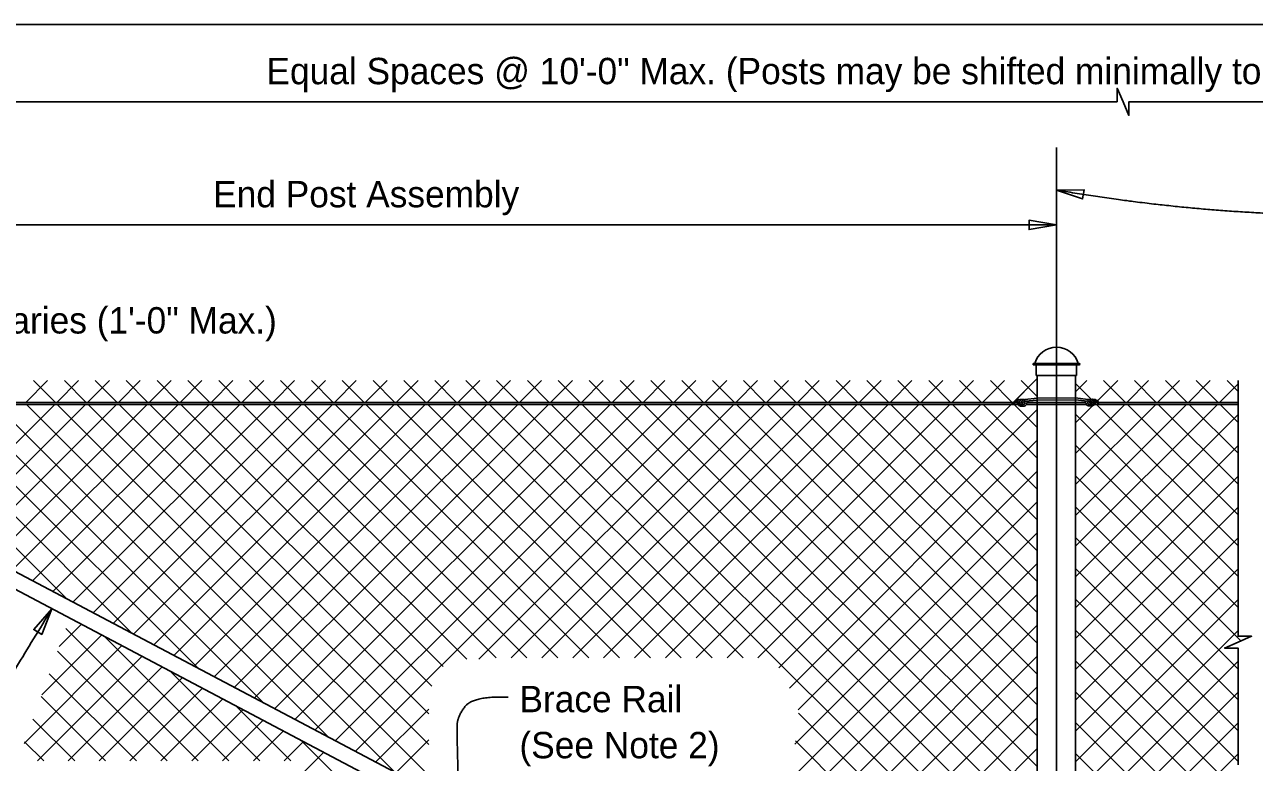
# Model space of a CAD drawing. Extents: x 0 to 41.1, y 0 to 25.9.
# Drawn here: x 6.74 to 16.13, y 20.31 to 25.95 of the extents above; entities that cross this region are included whole.
import ezdxf

# ---------------------------------------------------------------- set-up
doc = ezdxf.new("R2010")
doc.units = 0
for name, color, linetype in [('ActivePts-ConstElements', 7, 'Continuous'), ('CL_Major', 7, 'Continuous'), ('Dimension', 7, 'Continuous'), ('Miscellaneous', 7, 'Continuous'), ('Miscellaneous1', 7, 'Continuous'), ('SteelMisc', 7, 'Continuous'), ('SteelMisc_h', 7, 'Continuous'), ('TextStructures', 7, 'Continuous')]:
    doc.layers.add(name, color=color, linetype=linetype)

msp = doc.modelspace()

# ---------------------------------------------------------------- linework, layer by layer
at = {"layer": 'ActivePts-ConstElements'}
msp.add_lwpolyline([(0, 0), (41.0506, 0), (41.0506, 25.9461), (0, 25.9461)], close=True, dxfattribs=at)
at = {"layer": 'CL_Major'}
msp.add_line((14.615, 25.0052), (14.615, 14.7584), dxfattribs=at)
at = {"layer": 'Dimension'}
for p, q in [((0.2352, 25.3556), (13.615, 25.3556)), ((4.615, 24.4146), (14.615, 24.4146))]:
    msp.add_line(p, q, dxfattribs=at)
for points in [[(13.615, 25.3556), (15.0787, 25.3556), (15.0787, 25.4589), (15.1237, 25.3556), (15.1687, 25.2523), (15.1687, 25.3556), (28.4596, 25.3556)], [(16.002, 23.2265), (16.002, 21.2702), (16.1053, 21.2702), (16.002, 21.2252), (15.8987, 21.1802), (16.002, 21.1802), (16.002, 20.2867)]]:
    msp.add_lwpolyline(points, dxfattribs=at)
for points in [[(14.615, 24.6814), (14.815, 24.6135), (14.8262, 24.6832)], [(14.615, 24.4146), (14.4068, 24.4499), (14.4068, 24.3793)], [(6.945, 21.4806), (6.8059, 21.3216), (6.8661, 21.2847)]]:
    msp.add_lwpolyline(points, close=True, dxfattribs=at)
for points in [[(18.5966, 24.4827), (17.7933, 24.4827), (16.4039, 24.4827), (15.2225, 24.5773), (14.615, 24.6814)], [(6.6174, 20.081), (6.4865, 20.0669), (6.3036, 20.1341), (6.3121, 20.4608), (6.945, 21.4806)], [(10.4281, 20.8052), (10.1586, 20.8133), (10.0405, 20.6549), (10.0376, 20.5337), (10.0422, 20.3659), (10.0503, 19.9529)]]:
    msp.add_open_spline(points, degree=2, dxfattribs=at)
at = {"layer": 'Miscellaneous'}
for p, q in [((6.745, 23.0578), (6.9116, 23.2245)), ((6.8042, 23.2245), (6.9709, 23.0578)), ((6.9807, 23.0578), (7.1473, 23.2245)), ((7.0399, 23.2245), (7.2066, 23.0578)), ((7.2164, 23.0578), (7.383, 23.2245)), ((7.2756, 23.2245), (7.4423, 23.0578)), ((7.4521, 23.0578), (7.6187, 23.2245)), ((7.5113, 23.2245), (7.678, 23.0578)), ((7.6878, 23.0578), (7.8544, 23.2245)), ((7.747, 23.2245), (7.9137, 23.0578)), ((7.9235, 23.0578), (8.0901, 23.2245)), ((7.9827, 23.2245), (8.1494, 23.0578)), ((8.1592, 23.0578), (8.3258, 23.2245)), ((8.2184, 23.2245), (8.3851, 23.0578)), ((8.3949, 23.0578), (8.5615, 23.2245)), ((8.4541, 23.2245), (8.6208, 23.0578)), ((8.6306, 23.0578), (8.7972, 23.2245)), ((8.6898, 23.2245), (8.8565, 23.0578)), ((8.8663, 23.0578), (9.0329, 23.2245)), ((8.9255, 23.2245), (9.0922, 23.0578)), ((9.102, 23.0578), (9.2687, 23.2245)), ((9.1612, 23.2245), (9.3279, 23.0578)), ((9.3377, 23.0578), (9.5044, 23.2245)), ((9.3969, 23.2245), (9.5636, 23.0578)), ((9.5734, 23.0578), (9.7401, 23.2245)), ((9.6326, 23.2245), (9.7993, 23.0578)), ((9.8091, 23.0578), (9.9758, 23.2245)), ((9.8683, 23.2245), (10.035, 23.0578)), ((10.0448, 23.0578), (10.2115, 23.2245)), ((10.104, 23.2245), (10.2707, 23.0578)), ((10.2805, 23.0578), (10.4472, 23.2245)), ((10.3397, 23.2245), (10.5064, 23.0578)), ((10.5162, 23.0578), (10.6829, 23.2245)), ((10.5754, 23.2245), (10.7421, 23.0578)), ((10.7519, 23.0578), (10.9186, 23.2245)), ((10.8111, 23.2245), (10.9778, 23.0578)), ((10.9876, 23.0578), (11.1543, 23.2245)), ((11.0468, 23.2245), (11.2135, 23.0578)), ((11.2233, 23.0578), (11.39, 23.2245)), ((11.2825, 23.2245), (11.4492, 23.0578)), ((11.459, 23.0578), (11.6257, 23.2245)), ((11.5182, 23.2245), (11.6849, 23.0578)), ((11.6947, 23.0578), (11.8614, 23.2245)), ((11.7539, 23.2245), (11.9206, 23.0578)), ((11.9304, 23.0578), (12.0971, 23.2245)), ((11.9896, 23.2245), (12.1563, 23.0578)), ((12.1661, 23.0578), (12.3328, 23.2245)), ((12.2253, 23.2245), (12.392, 23.0578)), ((12.336, 21.1064), (14.4692, 23.2396)), ((12.4018, 23.0578), (12.5685, 23.2245)), ((12.461, 23.2245), (12.6277, 23.0578)), ((12.6375, 23.0578), (12.8042, 23.2245)), ((12.6967, 23.2245), (12.8634, 23.0578)), ((12.8732, 23.0578), (13.0399, 23.2245)), ((12.9324, 23.2245), (13.0991, 23.0578)), ((13.1089, 23.0578), (13.2756, 23.2245)), ((13.1681, 23.2245), (13.3348, 23.0578)), ((13.3446, 23.0578), (13.5113, 23.2245)), ((13.4038, 23.2245), (13.5705, 23.0578)), ((13.5803, 23.0578), (13.747, 23.2245)), ((13.6396, 23.2245), (13.8062, 23.0578)), ((13.816, 23.0578), (13.9827, 23.2245)), ((13.8753, 23.2245), (14.0419, 23.0578)), ((14.0517, 23.0578), (14.2184, 23.2245)), ((14.111, 23.2245), (14.2776, 23.0578)), ((14.2874, 23.0578), (14.4541, 23.2245)), ((14.3467, 23.2245), (14.4692, 23.1019)), ((14.7609, 23.1379), (14.8475, 23.2245)), ((14.7609, 23.2036), (14.8832, 23.0814)), ((14.928, 23.0694), (15.0832, 23.2245)), ((14.9757, 23.2245), (15.1424, 23.0578)), ((15.1522, 23.0578), (15.3189, 23.2245)), ((15.2114, 23.2245), (15.3781, 23.0578)), ((15.3879, 23.0578), (15.5546, 23.2245)), ((15.4471, 23.2245), (15.6138, 23.0578)), ((15.6236, 23.0578), (15.7903, 23.2245)), ((15.6828, 23.2245), (15.8495, 23.0578)), ((15.8593, 23.0578), (16.002, 23.2005)), ((15.9185, 23.2245), (16.002, 23.1411)), ((5.8071, 23.0431), (7.5577, 21.2925)), ((6.0252, 22.1023), (6.9659, 23.0431)), ((6.0428, 23.0431), (8.0575, 21.0283)), ((6.1794, 22.0209), (7.2016, 23.0431)), ((6.2785, 23.0431), (8.5574, 20.7642)), ((6.3336, 21.9394), (7.4373, 23.0431)), ((6.4878, 21.8579), (7.673, 23.0431)), ((6.5142, 23.0431), (9.0572, 20.5)), ((6.642, 21.7764), (7.9087, 23.0431)), ((6.7499, 23.0431), (9.5571, 20.2359)), ((6.7962, 21.6949), (8.1444, 23.0431)), ((6.9504, 21.6134), (8.3801, 23.0431)), ((6.9856, 23.0431), (9.8224, 20.2063)), ((7.1046, 21.5319), (8.6158, 23.0431)), ((7.2213, 23.0431), (9.8224, 20.442)), ((7.2589, 21.4504), (8.8515, 23.0431)), ((7.4131, 21.3689), (9.0872, 23.0431)), ((7.457, 23.0431), (9.8224, 20.6777)), ((7.5673, 21.2874), (9.3229, 23.0431)), ((7.6927, 23.0431), (9.8467, 20.8891)), ((7.7215, 21.2059), (9.5586, 23.0431)), ((7.8757, 21.1244), (9.7943, 23.0431)), ((7.9284, 23.0431), (9.9312, 21.0403)), ((8.0299, 21.0429), (10.03, 23.0431)), ((8.1641, 23.0431), (10.1124, 21.0948)), ((8.1841, 20.9614), (10.2657, 23.0431)), ((8.3383, 20.88), (10.5014, 23.0431)), ((8.3998, 23.0431), (10.3365, 21.1064)), ((8.4925, 20.7985), (10.7372, 23.0431)), ((8.6355, 23.0431), (10.5722, 21.1064)), ((8.6467, 20.717), (10.9729, 23.0431)), ((8.8009, 20.6355), (11.2086, 23.0431)), ((8.8712, 23.0431), (10.8079, 21.1064)), ((8.9552, 20.554), (11.4443, 23.0431)), ((9.1069, 23.0431), (11.0436, 21.1064)), ((9.1094, 20.4725), (11.68, 23.0431)), ((9.2636, 20.391), (11.9157, 23.0431)), ((9.3426, 23.0431), (11.2793, 21.1064)), ((9.5783, 23.0431), (11.515, 21.1064)), ((9.814, 23.0431), (11.7507, 21.1064)), ((10.0497, 23.0431), (11.9864, 21.1064)), ((10.2043, 21.096), (12.1514, 23.0431)), ((10.2854, 23.0431), (12.2221, 21.1064)), ((10.4504, 21.1064), (12.3871, 23.0431)), ((10.5211, 23.0431), (14.4692, 19.095)), ((10.6861, 21.1064), (12.6228, 23.0431)), ((10.7568, 23.0431), (14.4692, 19.3307)), ((10.9218, 21.1064), (12.8585, 23.0431)), ((10.9925, 23.0431), (14.4692, 19.5664)), ((11.1575, 21.1064), (13.0942, 23.0431)), ((11.2282, 23.0431), (14.4692, 19.8021)), ((11.3932, 21.1064), (13.3299, 23.0431)), ((11.4639, 23.0431), (14.4692, 20.0378)), ((11.6289, 21.1064), (13.5656, 23.0431)), ((11.6996, 23.0431), (14.4692, 20.2735)), ((11.8646, 21.1064), (13.8013, 23.0431)), ((11.9353, 23.0431), (14.4692, 20.5092)), ((12.1003, 21.1064), (14.037, 23.0431)), ((12.1003, 21.1064), (14.037, 23.0431)), ((12.1711, 23.0431), (14.4692, 20.7449)), ((12.4068, 23.0431), (14.4692, 20.9806)), ((12.6425, 23.0431), (14.4692, 21.2163)), ((12.8782, 23.0431), (14.4692, 21.452)), ((13.1139, 23.0431), (14.4692, 21.6877)), ((13.3496, 23.0431), (14.4692, 21.9234)), ((13.5853, 23.0431), (14.4692, 22.1591)), ((13.821, 23.0431), (14.4692, 22.3948)), ((14.0567, 23.0431), (14.4692, 22.6305)), ((14.2924, 23.0431), (14.4692, 22.8662)), ((14.7609, 21.9594), (15.8446, 23.0431)), ((14.7609, 22.4308), (15.3732, 23.0431)), ((14.7609, 22.6665), (15.1375, 23.0431)), ((14.7609, 22.9022), (14.8904, 23.0317)), ((14.7653, 22.1995), (15.6089, 23.0431)), ((14.9165, 23.0578), (14.921, 23.0623)), ((14.9214, 23.0431), (16.002, 21.9626)), ((15.1572, 23.0431), (16.002, 22.1983)), ((15.3929, 23.0431), (16.002, 22.434)), ((15.6286, 23.0431), (16.002, 22.6697)), ((15.8643, 23.0431), (16.002, 22.9054)), ((12.4951, 21.0298), (14.4692, 23.0039)), ((14.7609, 22.9679), (16.002, 21.7268)), ((14.7609, 21.7237), (16.002, 22.9648)), ((5.7518, 22.8627), (7.0578, 21.5566)), ((12.5756, 20.8746), (14.4692, 22.7682)), ((14.7609, 22.7322), (16.002, 21.4911)), ((14.7609, 21.488), (16.002, 22.7291)), ((12.6439, 20.7072), (14.4692, 22.5325)), ((14.7609, 22.4965), (16.023, 21.2344)), ((14.7609, 21.2523), (16.002, 22.4934)), ((12.6167, 20.4443), (14.4692, 22.2968)), ((14.7609, 22.2608), (16.002, 21.0197)), ((14.7609, 21.0166), (16.002, 22.2577)), ((11.5767, 19.1686), (14.4692, 22.0611)), ((14.7609, 22.0251), (16.002, 20.784)), ((14.7609, 20.7809), (16.002, 22.022)), ((11.7309, 19.0871), (14.4692, 21.8254)), ((14.7609, 21.7894), (16.002, 20.5483)), ((14.7609, 20.5452), (16.002, 21.7863)), ((11.8851, 19.0056), (14.4692, 21.5897)), ((14.7609, 21.5537), (16.002, 20.3126)), ((14.7609, 20.3095), (16.002, 21.5506)), ((7.0006, 21.1922), (7.1701, 21.3617)), ((7.0502, 21.3286), (8.0609, 20.3178)), ((12.0393, 18.9241), (14.4692, 21.354)), ((6.8661, 20.822), (7.3243, 21.2802)), ((7.3455, 21.269), (8.2966, 20.3178)), ((14.7609, 21.318), (16.002, 20.0769)), ((14.7609, 20.0738), (16.002, 21.3149)), ((6.7317, 20.4518), (7.4785, 21.1987)), ((6.9874, 21.1557), (7.8252, 20.3178)), ((6.8334, 20.3178), (7.6327, 21.1172)), ((12.1936, 18.8426), (14.4692, 21.1183)), ((14.7609, 21.0823), (16.002, 19.8412)), ((14.7609, 19.8381), (16.002, 21.0792)), ((6.9246, 20.9828), (7.5895, 20.3178)), ((7.0691, 20.3178), (7.7869, 21.0357)), ((7.3048, 20.3178), (7.9412, 20.9542)), ((7.8453, 21.0048), (8.5323, 20.3178)), ((7.5405, 20.3178), (8.0954, 20.8727)), ((12.3478, 18.7611), (14.4692, 20.8826)), ((6.8618, 20.8099), (7.3538, 20.3178)), ((7.7762, 20.3178), (8.2496, 20.7912)), ((14.7609, 20.8466), (16.002, 19.6055)), ((14.7609, 19.6024), (16.002, 20.8435)), ((8.0119, 20.3178), (8.4038, 20.7097)), ((8.3452, 20.7407), (8.768, 20.3178)), ((9.4178, 20.3095), (9.8224, 20.7141)), ((12.6449, 20.6836), (14.4692, 18.8593)), ((6.7989, 20.637), (7.1181, 20.3178)), ((8.2476, 20.3178), (8.558, 20.6282)), ((12.502, 18.6796), (14.4692, 20.6469)), ((14.7609, 20.6109), (16.002, 19.3698)), ((14.7609, 19.3667), (16.002, 20.6078)), ((8.4833, 20.3178), (8.7122, 20.5467)), ((8.845, 20.4766), (11.9157, 17.4059)), ((9.572, 20.228), (9.8224, 20.4784)), ((6.7361, 20.4641), (6.8824, 20.3178)), ((8.719, 20.3178), (8.8664, 20.4652)), ((8.8145, 20.1777), (9.0206, 20.3838)), ((12.6214, 20.4714), (14.4692, 18.6236)), ((12.6562, 18.5982), (14.4692, 20.4112)), ((14.7609, 20.3752), (15.9395, 19.1966)), ((14.7609, 19.131), (16.002, 20.3721))]:
    msp.add_line(p, q, dxfattribs=at)
at = {"layer": 'Miscellaneous1'}
msp.add_lwpolyline([(0, 25.9461), (41.0506, 25.9461), (41.0506, 0), (0, 0)], close=True, dxfattribs=at)
at = {"layer": 'SteelMisc'}
for p, q in [((14.4427, 23.3564), (14.7873, 23.3564)), ((14.7873, 23.3442), (14.4427, 23.3442)), ((14.461, 23.2645), (14.461, 23.3442)), ((14.7691, 23.2645), (14.7691, 23.3442)), ((14.7691, 23.2645), (14.461, 23.2645)), ((14.4692, 17.6192), (14.4692, 23.2644)), ((14.7609, 17.6192), (14.7609, 23.2644)), ((5.8052, 23.0578), (14.2941, 23.0578)), ((5.8052, 23.0431), (14.3207, 23.0431)), ((14.304, 23.0578), (14.3172, 23.0578)), ((14.4692, 23.0904), (14.3743, 23.0793)), ((14.4692, 23.0759), (14.3766, 23.0664)), ((14.3856, 23.0431), (14.4692, 23.0431)), ((14.387, 23.0578), (14.4692, 23.0578)), ((14.4692, 23.0904), (14.7604, 23.0921)), ((14.4692, 23.0759), (14.7604, 23.0776)), ((14.7604, 23.0921), (14.8547, 23.081)), ((14.7604, 23.0776), (14.8525, 23.0682)), ((14.7609, 23.0578), (14.8413, 23.0578)), ((14.7609, 23.0431), (14.8439, 23.0431)), ((14.9067, 23.0431), (16.002, 23.0431)), ((14.9116, 23.0578), (14.9269, 23.0578)), ((14.9353, 23.0578), (16.002, 23.0578)), ((14.2677, 17.7466), (5.0181, 22.6346)), ((14.2117, 17.6406), (4.962, 22.5285))]:
    msp.add_line(p, q, dxfattribs=at)
for centre, start, end in [((14.4429, 23.3502), 91.1647, 268.8353), ((14.7872, 23.3502), 271.1647, 88.8353)]:
    msp.add_arc(centre, 0.00613, start, end, dxfattribs=at)
for centre, major_axis, ratio, start_param, end_param in [((14.6157, 23.3154), (0.1711, 0), 0.957868, 0.252602, 2.888574), ((14.3283, 23.0436), (0.0373, 0), 0.957868, 1.486836, 3.108042), ((14.3494, 23.0039), (-0.0724, 0), 0.957868, 5.162149, 5.652106), ((14.3419, 23.0555), (-0.0249, 0), 0.957868, 6.009018, 7.089857), ((14.3408, 23.058), (0.023, 0), 0.957868, 1.29026, 2.970541), ((14.3433, 23.0515), (0.0231, 0), 0.957868, 3.779554, 4.879821), ((14.3595, 23.0527), (0.0295, 0), 0.957868, 1.220941, 4.039556), ((14.373, 23.0544), (-0.0303, -0.0108), 0.724765, 4.35367, 6.324556), ((14.3494, 23.0458), (0.0206, -0.0021), 0.798607, 4.32653, 5.220153), ((14.3629, 23.0458), (0.0206, -0.0021), 0.798607, 3.333154, 5.220153), ((14.3697, 23.0504), (-0.0139, 0), 0.957868, 5.22362, 6.905413), ((14.364, 23.048), (-0.00795, 0), 0.957868, 6.140374, 9.314262), ((14.3781, 23.0415), (-0.0259, 0), 0.957868, 4.777514, 5.62749), ((14.3624, 23.0538), (0.0119, 0), 0.957868, 5.725876, 7.416677), ((14.3555, 23.0646), (0.0391, 0), 0.957868, 5.082588, 5.41974), ((14.3624, 23.0538), (0.0119, 0), 0.957868, 5.639684, 5.723117), ((14.3626, 23.0525), (0.0251, 0), 0.957868, 5.531357, 6.227833), ((14.3626, 23.0525), (0.0251, 0), 0.957868, 0.407687, 0.609214), ((14.8661, 23.0543), (-0.0251, 0), 0.957868, 0.055352, 0.751829), ((14.8661, 23.0543), (-0.0251, 0), 0.957868, 5.673972, 5.875498), ((14.8732, 23.0664), (-0.0391, 0), 0.957868, 0.863445, 1.200597), ((14.8556, 23.0562), (0.0303, -0.0108), 0.724765, 6.241815, 8.212701), ((14.8506, 23.0433), (0.0259, 0), 0.957868, 0.655696, 1.505671), ((14.8663, 23.0556), (-0.0119, 0), 0.957868, 5.149694, 6.840495), ((14.8663, 23.0556), (-0.0119, 0), 0.957868, 0.560069, 0.643501), ((14.8646, 23.0498), (0.00795, 0), 0.957868, 3.252108, 6.425997), ((14.8658, 23.0476), (-0.0206, -0.0021), 0.798607, 1.063032, 2.950031), ((14.8691, 23.0544), (-0.0295, 0), 0.957868, 2.243629, 5.062245), ((14.859, 23.0521), (0.0139, 0), 0.957868, 5.660958, 7.342751), ((14.8792, 23.0476), (-0.0206, -0.0021), 0.798607, 1.063032, 1.956656), ((14.8879, 23.0598), (-0.023, 0), 0.957868, 3.312645, 4.992926), ((14.8853, 23.0533), (-0.0231, 0), 0.957868, 1.403365, 2.503632), ((14.9004, 23.0453), (-0.0373, 0), 0.957868, 3.175144, 4.79635), ((14.8867, 23.0573), (0.0249, 0), 0.957868, 5.476514, 6.557353), ((14.8792, 23.0056), (0.0724, 0), 0.957868, 0.631079, 1.121037)]:
    msp.add_ellipse(centre, major_axis=major_axis, ratio=ratio, start_param=start_param, end_param=end_param, dxfattribs=at)
at = {"layer": 'SteelMisc_h'}
for p, q in [((14.4692, 23.0578), (14.7609, 23.0578)), ((14.4692, 23.0431), (14.7609, 23.0431))]:
    msp.add_line(p, q, dxfattribs=at)

# ---------------------------------------------------------------- texts
at = {"layer": 'TextStructures'}
for s, p in [('Equal Spaces @ 10\'-0" Max. (Posts may be shifted minimally to meet required clearances)', (8.5826, 25.4902)), ('End Post Assembly', (8.1753, 24.5492)), ('Varies (1\'-0" Max.)', (6.4474, 23.5846)), ('Brace Rail', (10.5146, 20.6895)), ('(See Note 2)', (10.5146, 20.3375))]:
    msp.add_text(s, height=0.2016, dxfattribs=at).set_placement(p)

doc.saveas('drawing.dxf')
